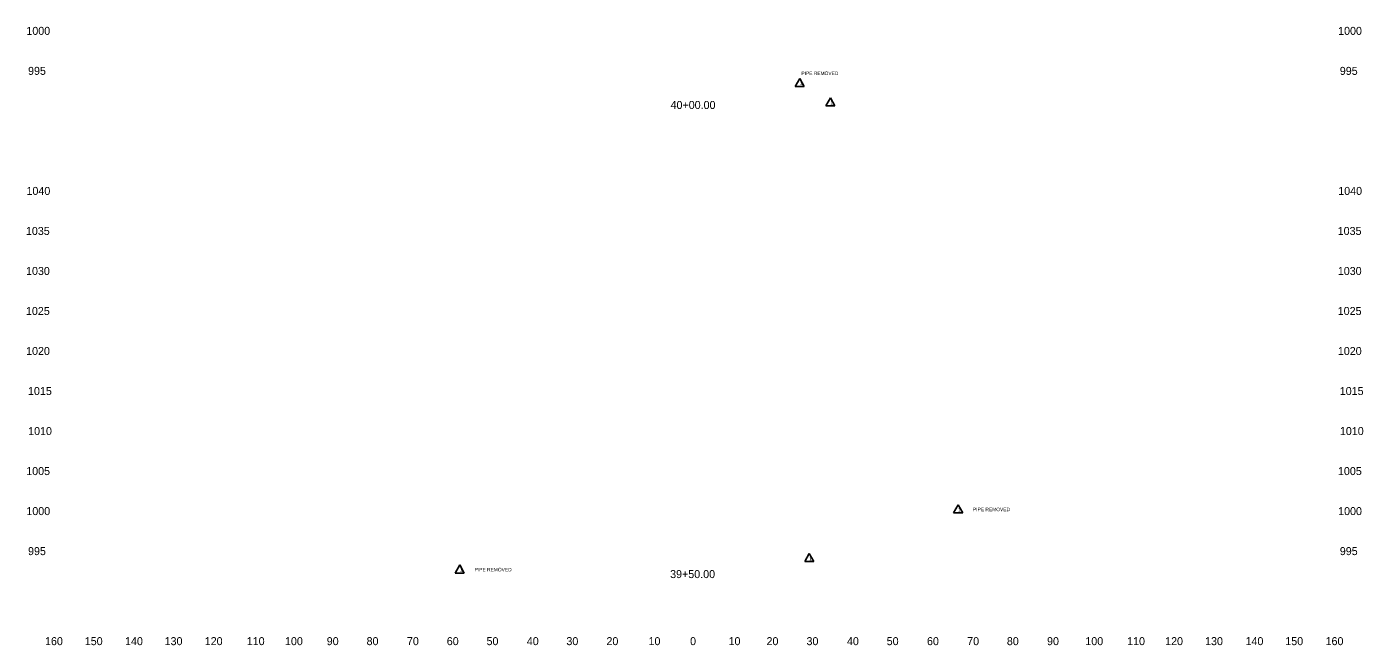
# Model space of a CAD drawing. Extents: x 4994 to 5843, y 4997 to 8804.
# Drawn here: x 4993.5 to 5327.5, y 8197.5 to 8352 of the extents above; entities that cross this region are included whole.
import ezdxf

# ---------------------------------------------------------------- set-up
doc = ezdxf.new("R2010")
doc.units = 0
for name, color, linetype in [('RD_SHT_TX', 7, 'Continuous'), ('RD_XS_TX_Offset', 7, 'Continuous'), ('RD_XS_TX_Station', 7, 'Continuous')]:
    doc.layers.add(name, color=color, linetype=linetype)

msp = doc.modelspace()

# ---------------------------------------------------------------- linework, layer by layer
at = {"layer": 'RD_SHT_TX'}
for p, q in [((5186.69, 8339.13), (5185.55, 8337.1)), ((5185.55, 8337.1), (5187.83, 8337.1)), ((5186.69, 8339.13), (5187.83, 8337.1)), ((5194.36, 8334.27), (5193.22, 8332.24)), ((5194.36, 8334.27), (5195.5, 8332.24)), ((5193.22, 8332.24), (5195.5, 8332.24)), ((5226.28, 8232.58), (5225.14, 8230.55)), ((5225.14, 8230.55), (5227.42, 8230.55)), ((5226.28, 8232.58), (5227.42, 8230.55)), ((5189.08, 8220.41), (5187.95, 8218.38)), ((5189.08, 8220.41), (5190.22, 8218.38)), ((5101.74, 8217.55), (5100.6, 8215.52)), ((5101.74, 8217.55), (5102.88, 8215.52)), ((5187.95, 8218.38), (5190.22, 8218.38)), ((5100.6, 8215.52), (5102.88, 8215.52))]:
    msp.add_line(p, q, dxfattribs=at)

# ---------------------------------------------------------------- texts
for s, p in [('PIPE REMOVED', (5187.11, 8339.96)), ('1', (5186.69, 8337.43)), ('1', (5194.36, 8332.57)), ('1', (5226.28, 8230.88)), ('PIPE REMOVED', (5229.99, 8230.97)), ('1', (5189.08, 8218.71)), ('1', (5101.74, 8215.85)), ('PIPE REMOVED', (5105.45, 8215.94))]:
    msp.add_text(s, height=0.88, dxfattribs=at).set_placement(p)
at = {"layer": 'RD_XS_TX_Offset'}
for s, p in [('1000', (4993.44, 8350)), ('1000', (5321.24, 8350)), ('995', (4993.86, 8340)), ('995', (5321.66, 8340)), ('1040', (4993.47, 8310)), ('1040', (5321.27, 8310)), ('1035', (4993.33, 8300)), ('1035', (5321.13, 8300)), ('1030', (4993.36, 8290)), ('1030', (5321.16, 8290)), ('1025', (4993.34, 8280)), ('1025', (5321.14, 8280)), ('1020', (4993.37, 8270)), ('1020', (5321.17, 8270)), ('1015', (4993.85, 8260)), ('1015', (5321.65, 8260)), ('1010', (4993.88, 8250)), ('1010', (5321.68, 8250)), ('1005', (4993.4, 8240)), ('1005', (5321.2, 8240)), ('1000', (4993.44, 8230)), ('1000', (5321.24, 8230)), ('995', (4993.86, 8220)), ('995', (5321.66, 8220)), ('160', (4998.1, 8197.5)), ('150', (5008.04, 8197.5)), ('140', (5018.1, 8197.5)), ('130', (5027.99, 8197.5)), ('120', (5038.01, 8197.5)), ('110', (5048.51, 8197.5)), ('100', (5058.07, 8197.5)), ('90', (5068.5, 8197.5)), ('80', (5078.46, 8197.5)), ('70', (5088.54, 8197.5)), ('60', (5098.5, 8197.5)), ('50', (5108.43, 8197.5)), ('40', (5118.5, 8197.5)), ('30', (5128.39, 8197.5)), ('20', (5138.4, 8197.5)), ('10', (5148.91, 8197.5)), ('0', (5159.3, 8197.5)), ('0', (5159.3, 8197.5)), ('10', (5168.91, 8197.5)), ('20', (5178.4, 8197.5)), ('30', (5188.39, 8197.5)), ('40', (5198.5, 8197.5)), ('50', (5208.43, 8197.5)), ('60', (5218.5, 8197.5)), ('70', (5228.54, 8197.5)), ('80', (5238.46, 8197.5)), ('90', (5248.5, 8197.5)), ('100', (5258.07, 8197.5)), ('110', (5268.51, 8197.5)), ('120', (5278.01, 8197.5)), ('130', (5287.99, 8197.5)), ('140', (5298.1, 8197.5)), ('150', (5308.04, 8197.5)), ('160', (5318.1, 8197.5))]:
    msp.add_text(s, height=2, dxfattribs=at).set_placement(p)
at = {"layer": 'RD_XS_TX_Station'}
for s, p in [('40+00.00', (5154.42, 8331.48)), ('39+50.00', (5154.31, 8214.26))]:
    msp.add_text(s, height=2, dxfattribs=at).set_placement(p)

doc.saveas('drawing.dxf')
